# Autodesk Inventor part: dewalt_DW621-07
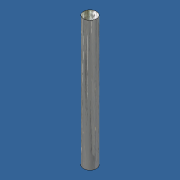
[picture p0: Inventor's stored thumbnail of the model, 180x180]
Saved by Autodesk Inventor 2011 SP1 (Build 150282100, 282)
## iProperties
Created: 2011-02
Part Number: dewalt_DW621-07
Material: 1.0037 St 37-2 / S235JR
Catalog Web Link: www.mittelmeyer.de
Document SubType Name: Modellieren
Designer: TMT
Manufacturer: Standard
Standards Organization: Custom
Density: 1 g/cm^3
Author: TMT
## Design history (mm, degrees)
sketch "Skizze2"
  geometry: C1 r 6 at (0, 0); 1 further point
  constraints: 1 centre point, 1 coincident
  dimensions: "d5" = 12 diameter of C1 (= durchmesser_01)
extrude "Extrusion2" new body sketch "Skizze2" distance "d6" = 120 (= hoehe_01); taper "d7" = 0 deg
node "Volumenkörper1"
node "Volumenkörpern"
node "Oberflächenkörpern"
other parameters: "durchmesser_01" = 12 [user parameter; used in 1 equation term], "hoehe_01" = 120 [user parameter; used in 1 equation term]
